// Mitsubishi GX Works2 project: FX2N PLC与四方变频器通讯   PLC: FX2N/FX2NC

PROGRAM MAIN
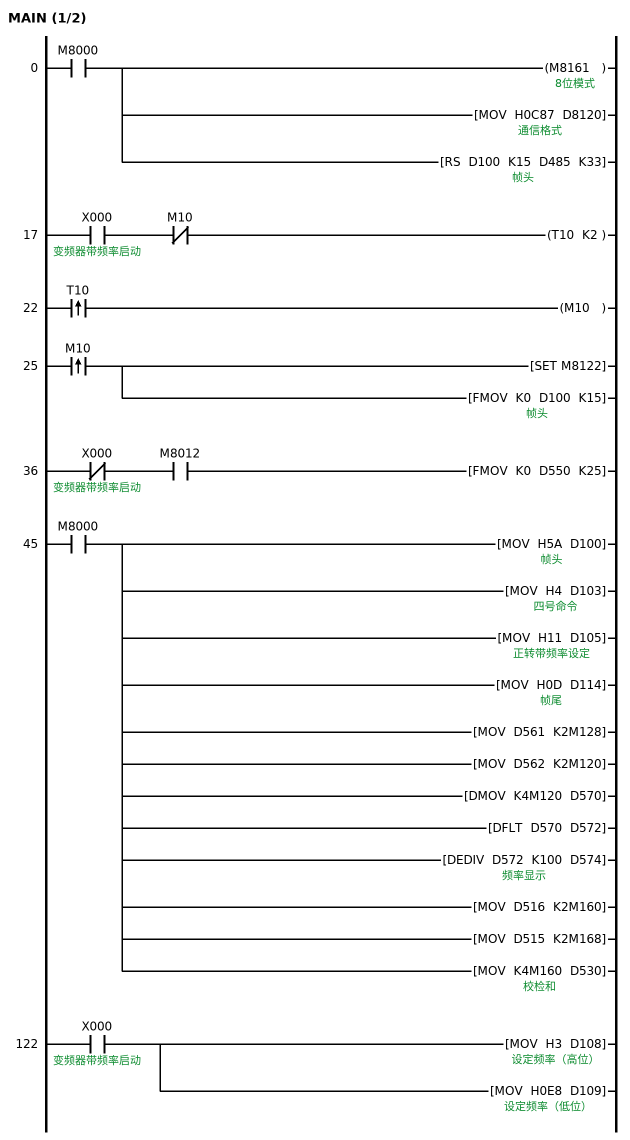
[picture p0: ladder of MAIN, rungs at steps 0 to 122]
0     LD      M8000
      OUT     M8161  ; 8位模式
      MOV     H0C87 D8120  ; 通信格式
      RS      D100 K15 D485 K33  ; 帧头
17    LD      X000  ; 变频器带频率启动
      ANI     M10
      OUT     T10 K2
22    LDP     T10
      OUT     M10
25    LDP     M10
      SET     M8122
      FMOV    K0 D100 K15
36    LDI     X000  ; 变频器带频率启动
      AND     M8012
      FMOV    K0 D550 K25
45    LD      M8000
      MOV     H5A D100
      MOV     H4 D103  ; 四号命令
      MOV     H11 D105  ; 正转带频率设定
      MOV     H0D D114  ; 帧尾
      MOV     D561 K2M128
      MOV     D562 K2M120
      DMOV    K4M120 D570
      DFLT    D570 D572
      DEDIV   D572 K100 D574  ; 频率显示
      MOV     D516 K2M160
      MOV     D515 K2M168
      MOV     K4M160 D530  ; 校检和
122   LD      X000  ; 变频器带频率启动
      MOV     H3 D108  ; 设定频率（高位）
      MOV     H0E8 D109  ; 设定频率（低位）
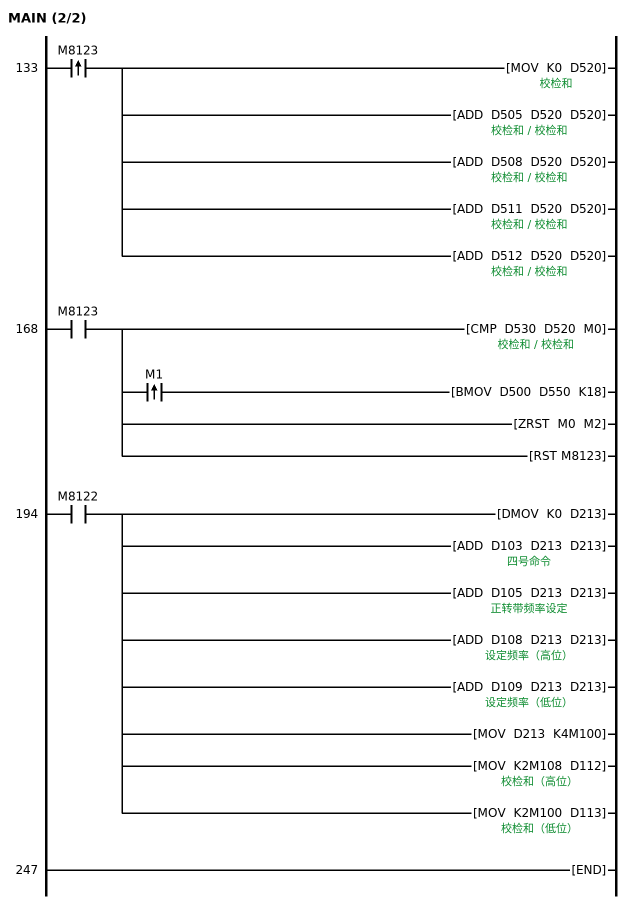
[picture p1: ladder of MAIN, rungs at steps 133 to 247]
133   LDP     M8123
      MOV     K0 D520  ; 校检和
      ADD     D505 D520 D520
      ADD     D508 D520 D520
      ADD     D511 D520 D520
      ADD     D512 D520 D520
168   LD      M8123
      CMP     D530 D520 M0
      MPS
      ANDP    M1
      BMOV    D500 D550 K18
      MPP
      ZRST    M0 M2
      RST     M8123
194   LD      M8122
      DMOV    K0 D213
      ADD     D103 D213 D213
      ADD     D105 D213 D213
      ADD     D108 D213 D213
      ADD     D109 D213 D213
      MOV     D213 K4M100
      MOV     K2M108 D112  ; 校检和（高位）
      MOV     K2M100 D113  ; 校检和（低位）
247   END
END_PROGRAM

// device comments not shown above
X001  ; 变频器停止
